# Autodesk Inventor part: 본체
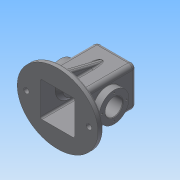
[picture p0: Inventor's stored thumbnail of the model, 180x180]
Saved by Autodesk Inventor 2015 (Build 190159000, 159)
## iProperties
Created: 2017-07
Part Number: 본체
Material: 일반
Document SubType Name: Modeling
Designer: owner
Density: 1 g/cm^3
Appearance: 기본값
Author: owner
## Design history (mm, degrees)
sketch "스케치1"
  geometry: L1 (37, -55)-(-37, -55); L2 (-37, -55)-(-37, 55); L3 (-37, 55)-(37, 55); L4 (37, 55)-(37, -55); L5 (37, -55)-(-37, 55); L6 (-37, -55)-(37, 55); 1 further point
  constraints: 12 end point, 2 midpoint, 2 parallel, 1 horizontal, 1 perpendicular
  dimensions: "d0" = 74 distance of L2.end L3.end; "d1" = 110 distance of L3.end L1.start
extrude "돌출1" new body sketch "스케치1" stored distance "d2" = 74; taper "d3" = 0 deg
fillet "모깎기1" dims "d4" = 8
feature "쉘1" dims "d5" = 5
sketch "스케치2" dims "d6" = 65, "d7" = 75
  geometry: L1 (-8, 66)-(-8, 8) reference; L2 (58, 0)-(0, 0) reference; L3 (66, 8)-(66, 66) reference; L4 (0, 74)-(58, 74) reference; A1 r 8 centre (0, 66) between (0, 74) and (-8, 66) reference; A2 r 8 centre (0, 8) between (-8, 8) and (0, 0) reference; A3 r 8 centre (58, 8) between (58, 0) and (66, 8) reference; A4 r 8 centre (58, 66) between (66, 66) and (58, 74) reference; 2 further points; 1 other entity
  constraints: 1 coincident, 2 other
extrude "돌출2" join sketch "스케치2" distance "d8" = 10; taper "d9" = 0 deg
sketch "스케치4"
  geometry: C1 r 27.5 at (29, -47); 1 further point
  constraints: 1 centre point, 1 coincident
  dimensions: "d10" = 55 diameter of C1
extrude "돌출3" join sketch "스케치4" distance "d11" = 13; taper "d12" = 0 deg
sketch "스케치5"
  geometry: C1 r 27.5 at (29, -47); 1 further point
  constraints: 1 centre point, 1 coincident
  dimensions: "d13" = 55 diameter of C1
extrude "돌출4" join sketch "스케치5" distance "d14" = 13; taper "d15" = 0 deg
sketch "스케치7"
  geometry: L1 (-50, 27.5)-(-50, -27.5) reference; L2 (-32, 0)-(-25, 0); L3 (-32, -55)-(-32, 47) reference; L4 (-32, 27.5)-(-25, 20.5); L5 (-25, 20.5)-(-25, 0); L6 (-32, 27.5)-(-32, 0); L7 (32, 47)-(32, -55) reference; 1 further point
  constraints: 8 end point, 2 point on line, 1 horizontal, 1 horizontal alignment, 1 perpendicular
  dimensions: "d16" = 7 distance between parallel lines of L3 L5; "d17" = 135 deg angle of L3 L4; "d91" = 55 diameter of L4.start L2
revolve "회전1" sketch "스케치7" stored, may be unused: angle "d19" = 90 deg
hole "구멍1" diameter "d22" = 32; stored, may be unused: countersink angle "d26" = 90 deg, drill point angle "d28" = 0 deg; dims "d20" = 10, "d21" = 10, "d23" = 6, "d24" = 4, "d25" = 2, "d27" = 8
sketch "스케치8"
  geometry: C1 r 16 at (0, 0) reference; 1 further point
  constraints: 1 vertical alignment
  dimensions: "d29" = 22.5 distance of point (0, 22.5) C1.centre
hole "구멍2" sketch "스케치8" at (0, 22.5) diameter "d30" = 3.242; stored, may be unused: countersink angle "d34" = 90 deg, drill point angle "d36" = 118 deg; dims "d31" = 8, "d32" = 4, "d33" = 2, "d35" = 10
node "작업 평면2"
  node "작업 평면1"
sketch "스케치9"
  geometry: L1 (-1.5, -9)-(38.5, -9); L2 (38.5, -9)-(38.5, -49); L3 (38.5, -49)-(-1.5, -49); L4 (-1.5, -49)-(-1.5, -9); L5 (-1.5, -9)-(38.5, -49); L6 (38.5, -9)-(-1.5, -49); 1 further point
  constraints: 12 end point, 2 midpoint, 2 parallel, 2 perpendicular, 1 horizontal
  dimensions: "d41" = 40 distance of L2.end L3.end
extrude "돌출5" join sketch "스케치9" stored distance "d42" = 13; taper "d43" = 5 deg
sketch "스케치10"
  geometry: 2 further points
  constraints: 1 coincident
hole "구멍3" sketch "스케치10" at (-18.5, 29) diameter "d44" = 21; stored, may be unused: countersink angle "d48" = 90 deg, drill point angle "d50" = 0 deg; dims "d45" = 8, "d46" = 28, "d47" = 4, "d49" = 10
sketch "스케치12"
  geometry: L1 (47, -37)-(-45, -37) reference; L2 (-45, -65)-(-45, 65) reference; L3 (27.194, -37)-(-45, -55); L4 (-45, -65)-(-45, 65) reference; L5 (-55, -65)-(-55, 65) reference; L6 (50, -29)-(50, -10.5) reference; L7 (50, -10.5)-(61, -10.5) reference; L8 (61, -10.5)-(61, -14) reference; L9 (61, -14)-(65, -14) reference; L10 (65, -14)-(65, -20) reference; L11 (65, -20)-(55, -20.875) reference; L12 (55, -20.875)-(55, -29) reference; L13 (47, -37)-(-45, -37) reference; L14 (-45, -37)-(-45, -65) reference; L15 (-45, -65)-(-55, -65) reference; L16 (-55, -65)-(-55, -32) reference; L17 (-55, -32)-(47, -32) reference; L18 (55, 29)-(55, 20.875) reference; L19 (55, 20.875)-(65, 20) reference; L20 (65, 20)-(65, 14) reference; L21 (65, 14)-(61, 14) reference; L22 (61, 14)-(61, 10.5) reference; L23 (61, 10.5)-(50, 10.5) reference; L24 (50, 10.5)-(50, 29) reference; L25 (47, 32)-(-55, 32) reference; L26 (-55, 32)-(-55, 65) reference; L27 (-55, 65)-(-45, 65) reference; L28 (-45, 65)-(-45, 37) reference; L29 (-45, 37)-(47, 37) reference; L30 (27.194, 37)-(-45, 55); A1 r 3 centre (47, -29) between (47, -32) and (50, -29) reference; A2 r 8 centre (47, -29) between (47, -37) and (55, -29) reference; A3 r 8 centre (47, 29) between (55, 29) and (47, 37) reference; A4 r 3 centre (47, 29) between (50, 29) and (47, 32) reference; 1 further point
  constraints: 4 end point, 4 point on line
  dimensions: "d52" = 14 deg angle of L3 L15; "d53" = 10 distance from line of L3.end L15; "d54" = 10 distance from line of L30.end L27; "d55" = 14 deg angle of L27 L30
  node "투영된 루프1"
  node "절단 모서리 투영1"
feature "리브2" dims "d62" = 1, "d63" = 10, "d64" = 0, "d65" = 0, "d66" = 1, "d67" = 1
chamfer "모따기1" distance "d69" = 1; stored, may be unused: second distance "d70" = 2, angle "d71" = 45 deg
fillet "모깎기3" dims "d72" = 0.5
fillet "모깎기4" dims "d73" = 0.5
sketch "스케치13"
  geometry: C1 r 5 at (-29, -37); C2 r 5 at (87, -37); 1 further point; 1 other entity
  constraints: 2 centre point, 2 horizontal alignment, 1 other
  dimensions: "d74" = 10 diameter of C1; "d75" = 10 diameter of C2; "d76" = 58 distance of C1.centre point (29, -37); "d77" = 116 distance of C2.centre C1.centre
extrude "돌출6" cut sketch "스케치13" stored distance "d78" = 13; taper "d79" = 0 deg
fillet "모깎기5" dims "d80" = 3
fillet "모깎기6" dims "d81" = 3
fillet "모깎기7" dims "d82" = 3
fillet "모깎기9" dims "d84" = 3
fillet "모깎기10" dims "d85" = 3
fillet "모깎기11" dims "d86" = 3
sketch "스케치14"
  geometry: L1 (46.011, 18)-(11.989, 18) reference; L2 (66, -89)-(66, 0) reference; 1 further point
  constraints: 1 other
  dimensions: "d87" = 30 distance from line of L1 point (29, -12); "d88" = 37 distance from line of point (29, -12) L2
feature "엠보싱1" sketch "스케치14" dims "d89" = 0.5, "d90" = 0
feature "리브3" dims "d92" = 1, "d93" = 10, "d94" = 0, "d95" = 0, "d96" = 1, "d97" = 1
fillet "모깎기12" dims "d98" = 2
fillet "모깎기13" dims "d99" = 2
fillet "모깎기14" dims "d100" = 0.5
node "솔리드1"
mirror "대칭1"
pattern_circular "원형 패턴1" dims angle "d38" = 360 deg
mirror "대칭2"
